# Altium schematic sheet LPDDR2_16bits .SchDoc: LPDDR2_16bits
size A3; Date: Not used; ApprovedBy: Not used; CheckedBy: Not used; Author: Not used; CompanyName: STMicroelectronics; DrawnBy: Not used; Engineer: Not used; Organization: Not used; Address1: Not used; Address2: Not used; Address3: Not used; Address4: Not used; DocumentNumber: Not used; Revision: Not used; SheetNumber: 7; SheetTotal: 7
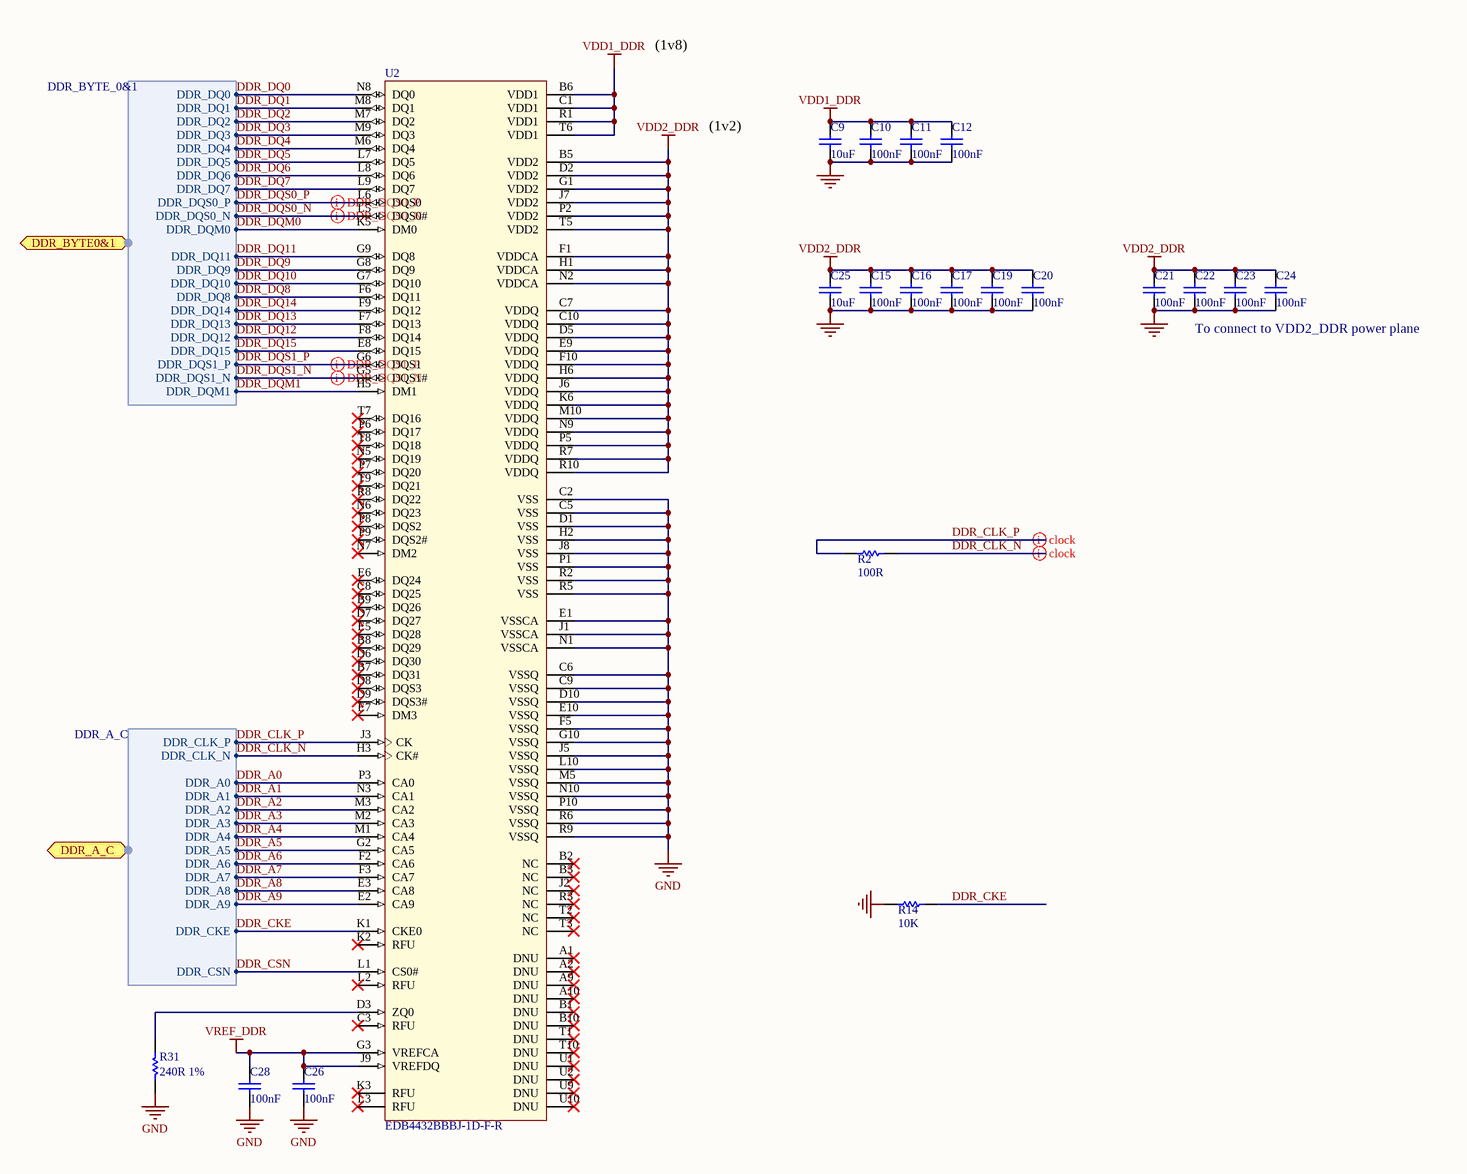
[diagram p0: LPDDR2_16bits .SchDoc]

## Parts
C9  value 10uF  [C0603]
C10  value 100nF  [C0402]
C11  value 100nF  [C0402]
C12  value 100nF  [C0402]
C15  value 100nF  [C0402]
C16  value 100nF  [C0402]
C17  value 100nF  [C0402]
C19  value 100nF  [C0402]
C20  value 100nF  [C0402]
C21  value 100nF  [C0402]
C22  value 100nF  [C0402]
C23  value 100nF  [C0402]
C24  value 100nF  [C0402]
C25  value 10uF  [C0603]
C26  value 100nF  [C0402]
C28  value 100nF  [C0402]
R2  value 100R  [R0402]
R14  value 10K  [R0402]
R31  value 240R 1%  [R0402]
U2  value EDB4432BBBJ-1D-F-R  [ICC_WFBGA134_SDP-SAC302_10X11P5_P065]

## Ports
DDR_A_C (harness DDR_A_C), DDR_BYTE0&1 (harness DDR_BYTE_0&1)

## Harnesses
DDR_BYTE_0&1: DDR_DQ0, DDR_DQ1, DDR_DQ2, DDR_DQ3, DDR_DQ4, DDR_DQ5, DDR_DQ6, DDR_DQ7, DDR_DQS0_P, DDR_DQS0_N, DDR_DQM0, DDR_DQ11, DDR_DQ9, DDR_DQ10, DDR_DQ8, DDR_DQ14, DDR_DQ13, DDR_DQ12, DDR_DQ15, DDR_DQS1_P, DDR_DQS1_N, DDR_DQM1
DDR_A_C: DDR_CLK_P, DDR_CLK_N, DDR_A0, DDR_A1, DDR_A2, DDR_A3, DDR_A4, DDR_A5, DDR_A6, DDR_A7, DDR_A8, DDR_A9, DDR_CSN, DDR_CKE

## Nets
GND: C9.1 C10.2 C11.2 C12.2 C15.2 C16.2 C17.2 C19.2 C20.2 C21.2 C22.2 C23.2 C24.2 C25.1 C26.2 C28.2 R14.1 R31.2 U2.C2(VSS) U2.C5(VSS) U2.C6(VSSQ) U2.C9(VSSQ) U2.D1(VSS) U2.D10(VSSQ) U2.E1(VSSCA) U2.E10(VSSQ) U2.F5(VSSQ) U2.G10(VSSQ) U2.H2(VSS) U2.J1(VSSCA) U2.J5(VSSQ) U2.J8(VSS) U2.L10(VSSQ) U2.M5(VSSQ) U2.N1(VSSCA) U2.N10(VSSQ) U2.P1(VSS) U2.P10(VSSQ) U2.R2(VSS) U2.R5(VSS) U2.R6(VSSQ) U2.R9(VSSQ)
VDD1_DDR: C9.2 C10.1 C11.1 C12.1 U2.B6(VDD1) U2.C1(VDD1) U2.R1(VDD1) U2.T6(VDD1)
VDD2_DDR: C15.1 C16.1 C17.1 C19.1 C20.1 C21.1 C22.1 C23.1 C24.1 C25.2 U2.B5(VDD2) U2.C7(VDDQ) U2.C10(VDDQ) U2.D2(VDD2) U2.D5(VDDQ) U2.E9(VDDQ) U2.F1(VDDCA) U2.F10(VDDQ) U2.G1(VDD2) U2.H1(VDDCA) U2.H6(VDDQ) U2.J6(VDDQ) U2.J7(VDD2) U2.K6(VDDQ) U2.M10(VDDQ) U2.N2(VDDCA) U2.N9(VDDQ) U2.P2(VDD2) U2.P5(VDDQ) U2.R7(VDDQ) U2.R10(VDDQ) U2.T5(VDD2)
VREF_DDR: C26.1 C28.1 U2.G3(VREFCA) U2.J9(VREFDQ)
DDR_A0: U2.P3(CA0) ; port DDR_A_C.DDR_A0
DDR_A1: U2.N3(CA1) ; port DDR_A_C.DDR_A1
DDR_A2: U2.M3(CA2) ; port DDR_A_C.DDR_A2
DDR_A3: U2.M2(CA3) ; port DDR_A_C.DDR_A3
DDR_A4: U2.M1(CA4) ; port DDR_A_C.DDR_A4
DDR_A5: U2.G2(CA5) ; port DDR_A_C.DDR_A5
DDR_A6: U2.F2(CA6) ; port DDR_A_C.DDR_A6
DDR_A7: U2.F3(CA7) ; port DDR_A_C.DDR_A7
DDR_A8: U2.E3(CA8) ; port DDR_A_C.DDR_A8
DDR_A9: U2.E2(CA9) ; port DDR_A_C.DDR_A9
DDR_CKE: R14.2 U2.K1(CKE0) ; port DDR_A_C.DDR_CKE
DDR_CLK_N: R2.2 U2.H3(CK#) ; port DDR_A_C.DDR_CLK_N
DDR_CLK_P: R2.1 U2.J3(CK) ; port DDR_A_C.DDR_CLK_P
DDR_CSN: U2.L1(CS0#) ; port DDR_A_C.DDR_CSN
DDR_DQ0: U2.N8(DQ0) ; port DDR_BYTE0&1.DDR_DQ0
DDR_DQ1: U2.M8(DQ1) ; port DDR_BYTE0&1.DDR_DQ1
DDR_DQ2: U2.M7(DQ2) ; port DDR_BYTE0&1.DDR_DQ2
DDR_DQ3: U2.M9(DQ3) ; port DDR_BYTE0&1.DDR_DQ3
DDR_DQ4: U2.M6(DQ4) ; port DDR_BYTE0&1.DDR_DQ4
DDR_DQ5: U2.L7(DQ5) ; port DDR_BYTE0&1.DDR_DQ5
DDR_DQ6: U2.L8(DQ6) ; port DDR_BYTE0&1.DDR_DQ6
DDR_DQ7: U2.L9(DQ7) ; port DDR_BYTE0&1.DDR_DQ7
DDR_DQ8: U2.F6(DQ11) ; port DDR_BYTE0&1.DDR_DQ8
DDR_DQ9: U2.G8(DQ9) ; port DDR_BYTE0&1.DDR_DQ9
DDR_DQ10: U2.G7(DQ10) ; port DDR_BYTE0&1.DDR_DQ10
DDR_DQ11: U2.G9(DQ8) ; port DDR_BYTE0&1.DDR_DQ11
DDR_DQ12: U2.F8(DQ14) ; port DDR_BYTE0&1.DDR_DQ12
DDR_DQ13: U2.F7(DQ13) ; port DDR_BYTE0&1.DDR_DQ13
DDR_DQ14: U2.F9(DQ12) ; port DDR_BYTE0&1.DDR_DQ14
DDR_DQ15: U2.E8(DQ15) ; port DDR_BYTE0&1.DDR_DQ15
DDR_DQM0: U2.K5(DM0) ; port DDR_BYTE0&1.DDR_DQM0
DDR_DQM1: U2.H5(DM1) ; port DDR_BYTE0&1.DDR_DQM1
DDR_DQS0_N: U2.L5(DQS0#) ; port DDR_BYTE0&1.DDR_DQS0_N
DDR_DQS0_P: U2.L6(DQS0) ; port DDR_BYTE0&1.DDR_DQS0_P
DDR_DQS1_N: U2.G5(DQS1#) ; port DDR_BYTE0&1.DDR_DQS1_N
DDR_DQS1_P: U2.G6(DQS1) ; port DDR_BYTE0&1.DDR_DQS1_P
NetR31_1: R31.1 U2.D3(ZQ0)

Not connected (* = marked no-connect by the designer): U2 A1(DNU)* A2(DNU)* A9(DNU)* A10(DNU)* B1(DNU)* B2(NC)* B3(NC)* B7(DQ31)* B8(DQ29)* B9(DQ26)* B10(DNU)* C3(RFU)* C8(DQ25)* D6(DQ30)* D7(DQ27)* D8(DQS3)* D9(DQS3#)* E5(DQ28)* E6(DQ24)* E7(DM3)* J2(NC)* K2(RFU)* K3(RFU)* L2(RFU)* L3(RFU)* N5(DQ19)* N6(DQ23)* N7(DM2)* P6(DQ17)* P7(DQ20)* P8(DQS2)* P9(DQS2#)* R3(NC)* R8(DQ22)* T1(DNU)* T2(NC)* T3(NC)* T7(DQ16)* T8(DQ18)* T9(DQ21)* T10(DNU)* U1(DNU)* U2(DNU)* U9(DNU)* U10(DNU)*

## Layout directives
differential pair: DDR_CLK_N, DDR_CLK_P, DDR_DQS0_N, DDR_DQS0_P, DDR_DQS1_N, DDR_DQS1_P

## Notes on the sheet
- (1v8)
- (1v2)
- To connect to VDD2_DDR power plane

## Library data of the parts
C9 C25 = MCD-01124: Capacitor, MLCC, 10uF, 10V, X5R, 10%, 0603, T=0.8mm; Manufacturer_Part_Number: GRM188R61A106KAAL; Manufacturer: MURATA; Provided_By: SUBCO; ECCN_US: EAR99; ECCN_EU: NEC
C10-C12 C15-C17 C19-C24 C26 C28 = MCD-00006: Capacitor, MLCC, 100nF, 16V, X7R, 10%, 0402, T=0.5mm; Manufacturer_Part_Number: CC0402KRX7R7BB104; Manufacturer: YAGEO; Alternate_Manufacturer_Part_Number: GCM155R71C104KA55D; Alternate_Manufacturer: MURATA; Provided_By: SUBCO; ECCN_US: EAR99; ECCN_EU: NEC
R2 = MCD-00067: Resistor,100R,0402,1%,1/16W; Manufacturer_Part_Number: RC0402FR-07100RL; Manufacturer: YAGEO; Provided_By: SUBCO; ECCN_US: EAR99; ECCN_EU: NEC
R14 = MCD-00053: Resistor,10K,0402,1%,1/16W; Manufacturer_Part_Number: RC0402FR-0710KL; Manufacturer: YAGEO; BMS_Part_Number: 9131590; Provided_By: SUBCO; ECCN_US: EAR99; ECCN_EU: NEC
R31 = MCD-00120: Resistor,240R,0402,1%,1/16W; Manufacturer_Part_Number: RC0402FR-07240RL; Manufacturer: YAGEO; ECCN_US: EAR99; ECCN_EU: NEC; Provided_By: SUBCO
U2 = MCD-01223: Memory,LPDDR2,4Gb,128Mbx32,533MHz,1066Mb/s,1V8/1V2,FBGA134; Part_Type: IC; Manufacturer: MICRON; Provided_By: SUBCO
